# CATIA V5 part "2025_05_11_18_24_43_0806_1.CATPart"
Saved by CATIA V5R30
Part number: 2025_05_11_18_24_43_0806_1
Definition: 2025_05_11_18_24_43_0806
Nomenclature: 2025_05_11_18_24_43_0806
Source: Unknown
Description: PART--DESC
Bounding box of the stored display mesh (mm): x -12.75 to 12.75, y -12.75 to 12.75, z 0 to 53
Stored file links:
  E:\Bakalarka\Model\Forma_v7\2025_05_11_18_24_43_0806_1.CATPart
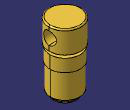
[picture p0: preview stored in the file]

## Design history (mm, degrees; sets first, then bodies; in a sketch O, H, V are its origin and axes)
Body1 "MANIFOLD_SOLID_BREP #164" (main body)
  Solid1: solid without history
